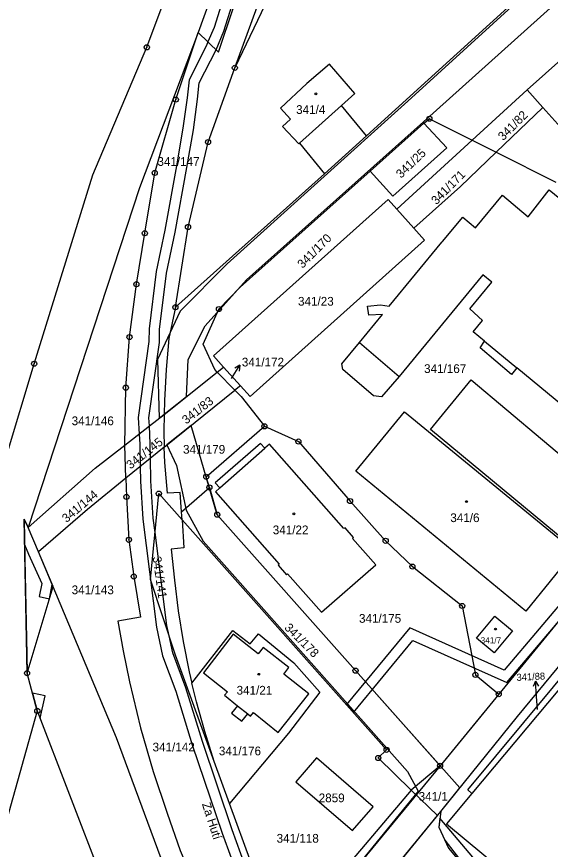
# Model space of a CAD drawing. Extents: x -562167 to -556918, y -1077891 to -1070763.
# Drawn here: x -558021.9 to -557917.9, y -1073189.3 to -1073027.2 of the extents above; entities that cross this region are included whole.
import ezdxf

# ---------------------------------------------------------------- set-up
doc = ezdxf.new("R2010")
doc.units = 0
for name, color, linetype in [('Hranice parcel', 7, 'Continuous'), ('Parcelní čísla', 7, 'Continuous'), ('Pop  PČ popisy', 7, 'Continuous'), ('Vnitřní kresba', 7, 'Continuous'), ('Věcná břemena k části', 7, 'Continuous'), ('Značky bodu BP', 7, 'Continuous'), ('Značky budov', 7, 'Continuous')]:
    doc.layers.add(name, color=color, linetype=linetype)

msp = doc.modelspace()

# ---------------------------------------------------------------- linework, layer by layer
at = {"layer": 'Hranice parcel'}
for p, q in [((-557978.42, -1073007.88), (-557986.56, -1073030.25)), ((-557907.19, -1073008.05), (-557953.76, -1073050.4)), ((-557990.91, -1073043.32), (-557986.56, -1073030.25)), ((-557933.18, -1073051.22), (-557922.44, -1073041.43)), ((-557922.44, -1073041.43), (-557919.41, -1073044.83)), ((-557919.41, -1073044.83), (-557928.5, -1073053.57)), ((-557909.28, -1073056.19), (-557919.41, -1073044.83)), ((-557953.04, -1073057.23), (-557942.56, -1073047.93)), ((-557953.76, -1073050.4), (-557961.97, -1073057.78)), ((-557947.88, -1073064.63), (-557933.18, -1073051.22)), ((-557933.18, -1073051.22), (-557928.5, -1073053.57)), ((-557928.5, -1073053.57), (-557916.86, -1073059.41)), ((-557961.97, -1073057.78), (-557990.99, -1073083.73)), ((-557978.35, -1073079.84), (-557953.04, -1073057.23)), ((-557947.88, -1073064.63), (-557944.57, -1073068.33)), ((-557982.82, -1073096.35), (-557981.6, -1073095.38)), ((-557978.3, -1073099.03), (-557981.6, -1073095.38)), ((-557993.2, -1073104.6), (-557982.82, -1073096.35)), ((-557982.82, -1073096.35), (-557983.3, -1073095.86)), ((-557979.38, -1073099.9), (-557982.82, -1073096.35)), ((-558000.85, -1073110.59), (-558000.64, -1073099.4)), ((-557993.15, -1073110.97), (-557979.38, -1073099.9)), ((-557978.3, -1073099.03), (-557979.38, -1073099.9)), ((-557979.38, -1073099.9), (-557978.18, -1073101.14)), ((-557993.14, -1073101.88), (-557993.2, -1073104.6)), ((-557978.18, -1073101.14), (-557973.65, -1073106.92)), ((-558000.64, -1073117.04), (-558000.85, -1073110.59)), ((-557993.15, -1073110.97), (-558000.64, -1073117.04)), ((-557993.03, -1073113.93), (-557993.15, -1073110.97)), ((-558000.64, -1073117.04), (-558000.52, -1073120.65)), ((-557989.8, -1073123.55), (-557984.37, -1073118.82)), ((-557989.7, -1073125.09), (-557989.8, -1073123.55)), ((-558017.66, -1073131.36), (-558019.64, -1073126.64)), ((-557905.93, -1073145.77), (-557933.22, -1073178.38)), ((-557928, -1073159.05), (-557939.43, -1073173)), ((-557980.44, -1073180.31), (-557983.42, -1073172.14)), ((-557939.43, -1073173), (-557945.06, -1073177.72)), ((-557957.38, -1073203.94), (-557939.31, -1073181.91))]:
    msp.add_line(p, q, dxfattribs=at)
for points in [[(-558023.91, -1073118.12), (-558023.87, -1073112.67), (-558018.5, -1073094.73), (-558007.07, -1073057.93), (-557996.56, -1073033.14), (-557957.14, -1072927.95), (-557940.88, -1072884.8)], [(-557828.77, -1072964.03), (-557832.02, -1072960.41), (-557849.58, -1072976.05), (-557850.4, -1072975.22), (-557852.25, -1072973.18), (-557902.56, -1073018.36), (-557900.74, -1073020.37), (-557901.86, -1073021.37), (-557901.06, -1073022.27), (-557922.44, -1073041.43)], [(-557986.56, -1073030.25), (-557982.57, -1073034.1), (-557976.61, -1073016.24), (-557974.32, -1073010.73), (-557971.33, -1073005.68), (-557965.93, -1072998.31), (-557952.35, -1072982.67), (-557941.8, -1072972.85)], [(-557979.41, -1073037.13), (-557974.34, -1073023.25), (-557969.19, -1073013.05), (-557961.67, -1072999.93), (-557956.79, -1072992.37), (-557951.58, -1072985.33)], [(-557958.24, -1072996.81), (-557969.89, -1073017.14), (-557979.41, -1073037.13)], [(-557986.56, -1073030.25), (-557997.97, -1073060.52), (-558019.64, -1073126.64)], [(-557990.99, -1073083.73), (-557988.53, -1073068.12), (-557984.62, -1073051.58), (-557979.41, -1073037.13)], [(-557953.76, -1073050.4), (-557958.64, -1073044.45), (-557956.03, -1073042.11), (-557960.96, -1073036.4), (-557965.35, -1073040.16), (-557970.52, -1073045), (-557968.56, -1073047.1), (-557970.12, -1073048.54), (-557966.96, -1073051.92), (-557966.81, -1073051.78), (-557961.97, -1073057.78)], [(-558000.64, -1073099.4), (-557999.93, -1073089.54), (-557998.58, -1073079.27), (-557996.94, -1073069.34), (-557995.02, -1073057.58), (-557990.91, -1073043.32)], [(-557942.56, -1073047.93), (-557938.12, -1073052.69), (-557948.63, -1073062.09), (-557953.04, -1073057.23)], [(-557942.56, -1073047.93), (-557941.51, -1073047.04), (-557933.18, -1073051.22)], [(-557928.5, -1073053.57), (-557935.44, -1073060.24), (-557944.57, -1073068.33)], [(-557907.63, -1073109.45), (-557924.45, -1073095.53), (-557925.5, -1073096.82), (-557931.62, -1073091.61), (-557930.74, -1073090.33), (-557932.96, -1073088.5), (-557931.14, -1073086.3), (-557933.62, -1073084.07), (-557929.32, -1073078.85), (-557931.08, -1073077.41), (-557947.37, -1073097.24), (-557950.81, -1073101.21), (-557952.39, -1073100.98), (-557958.38, -1073095.85), (-557958.54, -1073094.77), (-557955.13, -1073090.62), (-557950.62, -1073085.14), (-557953.33, -1073085.27), (-557953.54, -1073083.52), (-557951.06, -1073083.26), (-557949.32, -1073083.55), (-557939.09, -1073071.1), (-557938.95, -1073070.95), (-557934.98, -1073066.23), (-557932.52, -1073068.28), (-557927.25, -1073061.91), (-557922.29, -1073066.12), (-557918.16, -1073060.91), (-557884.44, -1073088.22)], [(-557981.6, -1073095.38), (-557983.55, -1073093.22), (-557949.57, -1073062.74), (-557947.88, -1073064.63)], [(-557944.57, -1073068.33), (-557942.47, -1073070.68), (-557976.44, -1073101.09), (-557978.3, -1073099.03)], [(-557983.3, -1073095.86), (-557985.61, -1073090.94), (-557982.51, -1073084.09), (-557978.35, -1073079.84)], [(-557990.99, -1073083.73), (-557992.26, -1073089.81), (-557992.79, -1073095.87), (-557993.14, -1073101.88)], [(-557912.95, -1073130.96), (-557941.31, -1073107.54), (-557933.38, -1073097.86), (-557912.52, -1073115.4)], [(-558000.85, -1073110.59), (-557996.03, -1073106.85), (-557993.2, -1073104.6)], [(-557993.2, -1073104.6), (-557993.27, -1073107.88), (-557993.15, -1073110.97)], [(-557913.26, -1073131.24), (-557922.7, -1073142.9), (-557955.83, -1073115.65), (-557946.34, -1073104.09), (-557913.26, -1073131.24)], [(-557984.37, -1073118.82), (-557984.98, -1073116.73), (-557973.65, -1073106.92)], [(-557973.65, -1073106.92), (-557967.03, -1073109.88), (-557956.97, -1073121.47), (-557950.03, -1073129.2), (-557944.82, -1073134.22), (-557935.12, -1073141.88), (-557932.55, -1073155.3), (-557928, -1073159.05)], [(-558019.64, -1073126.64), (-558006.61, -1073115.07), (-558000.85, -1073110.59)], [(-557969.37, -1073135.81), (-557969.15, -1073135.61), (-557962.54, -1073143.1), (-557951.95, -1073133.91), (-557956.51, -1073128.73), (-557956.29, -1073128.58), (-557957.94, -1073126.65), (-557958.16, -1073126.84), (-557972.65, -1073110.37), (-557973.57, -1073111.19), (-557974.4, -1073110.29), (-557983.25, -1073117.92), (-557982.35, -1073118.91), (-557983.2, -1073119.66), (-557970.77, -1073133.77), (-557970.99, -1073133.97), (-557969.37, -1073135.81)], [(-557989.8, -1073123.55), (-557990.05, -1073119.8), (-557992.55, -1073119.94), (-557993.03, -1073113.93)], [(-558000.64, -1073117.04), (-558008.11, -1073123.09), (-558017.66, -1073131.36)], [(-557984.37, -1073118.82), (-557982.83, -1073124.12), (-557955.89, -1073154.48), (-557939.43, -1073173)], [(-558000.52, -1073120.65), (-558000.04, -1073129.01), (-557999.11, -1073136.15), (-557997.8, -1073144.09), (-558002.18, -1073144.84), (-558001.16, -1073150.6), (-557999.9, -1073156.63), (-557997.77, -1073165.6), (-557995.29, -1073174.11), (-557992.59, -1073182.21), (-557990.03, -1073189.46), (-557987.35, -1073195.77), (-557983.68, -1073194.26), (-557982.33, -1073196.81), (-557981.76, -1073198.85), (-557981.57, -1073201.43), (-557982.14, -1073203.98), (-557983.75, -1073205.73), (-557985.87, -1073206.17)], [(-557983.42, -1073172.14), (-557990.96, -1073151.47), (-557995.82, -1073136.74), (-557994.21, -1073120.02), (-557989.7, -1073125.09)], [(-557896.87, -1073121.14), (-557897.99, -1073122.83), (-557900.41, -1073126.04), (-557904.25, -1073130.15), (-557928, -1073159.05)], [(-558017.89, -1073162.31), (-558019.89, -1073154.97), (-558020.46, -1073125.01), (-558019.64, -1073126.64)], [(-557989.7, -1073125.09), (-557989.34, -1073130.57), (-557991.78, -1073130.81), (-557991.16, -1073136.84), (-557990.48, -1073142.82), (-557989.46, -1073148.8), (-557988.32, -1073154.7), (-557987.77, -1073156.89)], [(-557945.06, -1073177.72), (-557951.46, -1073171.48), (-557949.84, -1073169.89), (-557989.7, -1073125.09)], [(-557988.88, -1073205.99), (-557991.98, -1073195.8), (-558002.46, -1073167.55), (-558017.66, -1073131.36)], [(-557939.31, -1073181.91), (-557924.34, -1073163.38), (-557903.65, -1073138.34), (-557899.86, -1073135.36), (-557897.5, -1073134.86), (-557893.95, -1073136.63), (-557873.45, -1073153.94), (-557872.45, -1073154.98)], [(-557925.34, -1073146.76), (-557928.91, -1073150.99), (-557932.3, -1073148.14), (-557928.73, -1073143.89), (-557925.34, -1073146.76)], [(-557933.22, -1073178.38), (-557934.05, -1073177.7), (-557906.42, -1073144.55), (-557905.54, -1073145.31)], [(-557987.77, -1073156.89), (-557979.78, -1073146.64), (-557976.42, -1073149.25), (-557974.83, -1073147.3), (-557967.94, -1073152.96), (-557962.85, -1073158.68), (-557968.95, -1073166.68), (-557980.44, -1073180.31)], [(-557970.95, -1073166.51), (-557965.02, -1073158.98), (-557969.85, -1073155.15), (-557968.89, -1073153.89), (-557973.86, -1073149.99), (-557974.84, -1073151.22), (-557979.76, -1073147.38), (-557985.54, -1073154.91), (-557980.86, -1073158.6), (-557981.39, -1073159.27), (-557978.88, -1073161.31), (-557980.03, -1073162.76), (-557978.05, -1073164.33), (-557976.9, -1073162.88), (-557976.34, -1073163.32), (-557975.78, -1073162.62), (-557970.95, -1073166.51)], [(-557983.42, -1073172.14), (-557985.27, -1073166.32), (-557986.86, -1073160.52), (-557987.77, -1073156.89)], [(-558017.89, -1073162.31), (-558032.09, -1073212.63), (-558035.15, -1073249.33), (-558039.97, -1073265.01), (-558041.24, -1073272.26), (-558045.55, -1073290.79), (-558055.77, -1073312.33), (-558066.64, -1073329.29), (-558067.37, -1073328.67), (-558071.91, -1073335.47), (-558071.45, -1073339.78), (-558072.38, -1073341.74), (-558078.52, -1073350.81)], [(-558017.89, -1073162.31), (-558005.3, -1073194.99), (-557999.34, -1073213.91)], [(-557963.49, -1073171.43), (-557967.51, -1073176.11), (-557956.46, -1073185.61), (-557952.45, -1073180.98), (-557963.49, -1073171.43)], [(-557945.06, -1073177.72), (-557964.79, -1073201.02), (-557968.13, -1073202.16), (-557970.23, -1073202.86)], [(-557933.22, -1073178.38), (-557938.16, -1073184.28), (-557924.03, -1073196.06), (-557926.52, -1073199.04), (-557917.14, -1073206.89), (-557900.5, -1073186.91)], [(-557970.23, -1073202.86), (-557971.99, -1073203.45), (-557980.44, -1073180.31)], [(-557939.31, -1073181.91), (-557939.68, -1073184.93), (-557937.77, -1073189.03), (-557931.69, -1073196.32), (-557936.68, -1073201.34), (-557924.3, -1073214.73)]]:
    msp.add_lwpolyline(points, dxfattribs=at)
at = {"layer": 'Pop  PČ popisy'}
for p, q in [((-557980.05, -1073097.58), (-557978.46, -1073095.03)), ((-557978.46, -1073095.03), (-557979.42, -1073095.62)), ((-557978.46, -1073095.03), (-557978.57, -1073096.15)), ((-557920.85, -1073156.54), (-557921.28, -1073157.57)), ((-557920.64, -1073159.53), (-557920.85, -1073156.54)), ((-557920.85, -1073156.54), (-557920.28, -1073157.5)), ((-557920.47, -1073162.06), (-557920.64, -1073159.53))]:
    msp.add_line(p, q, dxfattribs=at)
at = {"layer": 'Vnitřní kresba'}
for p, q in [((-557966.81, -1073051.78), (-557958.64, -1073044.45)), ((-557955.13, -1073090.62), (-557947.37, -1073097.24)), ((-557930.74, -1073090.33), (-557924.45, -1073095.53)), ((-557982.35, -1073118.91), (-557973.57, -1073111.19)), ((-557978.88, -1073161.31), (-557976.9, -1073162.88))]:
    msp.add_line(p, q, dxfattribs=at)
at = {"layer": 'Věcná břemena k části'}
for points in [[(-557822.11, -1072958), (-557824.2, -1072954.83), (-557832.14, -1072950.96), (-557839.71, -1072951.32), (-557846.26, -1072953.78), (-557883.58, -1072987.07), (-557945.69, -1073043.61), (-557980.87, -1073075.26), (-557990.05, -1073084.52), (-557994.46, -1073093.88), (-557994.12, -1073105.33), (-557988.84, -1073101.13), (-557988.53, -1073093.9), (-557985.16, -1073087.37), (-557977.13, -1073078.4), (-557942.64, -1073047.63), (-557878.66, -1072990.23), (-557843.73, -1072959.02), (-557840.12, -1072957.18), (-557833.96, -1072956.11), (-557830.07, -1072957.65), (-557825.42, -1072960.99)], [(-557985.61, -1073129.28), (-557959.92, -1073158.14), (-557945.8, -1073174.09), (-557943.7, -1073177.96), (-557960.77, -1073198.93), (-557964.79, -1073201.02), (-557971.99, -1073203.45), (-557986.64, -1073206.33), (-557988.88, -1073205.99), (-557985.92, -1073215.71), (-557980.83, -1073211.55), (-557974.16, -1073210.07), (-557963.9, -1073207.49), (-557961.96, -1073206.66), (-557959.95, -1073205.6), (-557957.38, -1073203.94), (-557939.31, -1073181.91), (-557935.6, -1073177.31), (-557955.89, -1073154.48), (-557982.83, -1073124.12), (-557987.89, -1073106.75), (-557992.63, -1073110.55), (-557990.75, -1073114.56), (-557988.87, -1073123.27)], [(-557944.74, -1073148.58), (-557926.4, -1073156.82), (-557898.45, -1073123.82), (-557890.09, -1073120.19), (-557888.89, -1073117.48), (-557899.68, -1073122.17), (-557926.95, -1073154.37), (-557945.32, -1073146.12), (-557957.67, -1073161.09), (-557956.32, -1073162.6)], [(-558019.89, -1073154.97), (-558014.83, -1073138.1), (-558017.66, -1073131.36), (-558019.64, -1073126.64), (-558020.46, -1073125.01), (-558020.31, -1073132.76), (-558019.96, -1073151.35)], [(-558014.99, -1073137.73), (-558017.66, -1073131.36), (-558019.64, -1073126.64), (-558020.46, -1073125.01), (-558020.36, -1073129.9), (-558019.58, -1073131.83), (-558016.98, -1073137.52), (-558017.5, -1073140.07), (-558015.54, -1073140.47)], [(-558018.83, -1073158.85), (-558017.89, -1073162.31), (-558017.34, -1073163.73), (-558016.36, -1073159.37)], [(-557945.06, -1073177.72), (-557964.79, -1073201.02), (-557968.13, -1073202.16), (-557971.99, -1073203.45), (-557986.64, -1073206.33), (-557988.88, -1073205.99), (-557985.92, -1073215.71), (-557980.83, -1073211.55), (-557965.16, -1073207.75), (-557957.1, -1073203.71), (-557939.95, -1073182.7)]]:
    msp.add_lwpolyline(points, close=True, dxfattribs=at)
for points in [[(-557979.03, -1073015.14), (-557983.45, -1073029.27), (-557984.64, -1073032.1), (-557984.93, -1073032.8), (-557988.33, -1073039.46), (-557988.69, -1073042.96), (-557989.51, -1073048.86), (-557990.79, -1073056.2), (-557993.03, -1073068.72), (-557994.75, -1073076.78), (-557996.11, -1073087.91), (-557996.14, -1073090.43), (-557998.23, -1073105.17), (-557998.05, -1073108.42), (-557997.93, -1073110.42), (-557997.85, -1073114.78), (-557997.8, -1073117.59), (-557997.33, -1073124.98), (-557994.66, -1073146.04), (-557993.47, -1073151.61), (-557990.92, -1073158.47), (-557987.69, -1073168.93), (-557981.87, -1073186.12), (-557978.4, -1073195.75)], [(-557976.54, -1073194.83), (-557979.93, -1073185.45), (-557985.74, -1073168.29), (-557988.98, -1073157.81), (-557991.5, -1073151.04), (-557992.21, -1073147.68), (-557992.63, -1073145.7), (-557994.94, -1073127.56), (-557995.29, -1073124.78), (-557995.75, -1073117.5), (-557995.83, -1073113.14), (-557995.89, -1073110.35), (-557996.03, -1073106.85), (-557996.18, -1073105.25), (-557994.09, -1073090.59), (-557994.06, -1073088.05), (-557992.72, -1073077.12), (-557991.02, -1073069.12), (-557988.77, -1073056.56), (-557987.49, -1073049.18), (-557986.65, -1073043.21), (-557986.33, -1073040.05), (-557983.05, -1073033.64), (-557981.53, -1073029.97), (-557977.08, -1073015.78)], [(-557957.38, -1073203.94), (-557939.31, -1073181.91), (-557924.34, -1073163.38), (-557903.65, -1073138.34), (-557899.86, -1073135.36), (-557897.5, -1073134.86), (-557893.95, -1073136.63), (-557876.59, -1073151.28), (-557875.07, -1073152.58), (-557873.45, -1073153.94), (-557872.45, -1073154.98), (-557868.31, -1073151.46), (-557870.27, -1073149.44), (-557875.14, -1073146.31), (-557882.72, -1073138.43), (-557890.2, -1073132), (-557891.89, -1073129.49), (-557893.05, -1073127.79), (-557904.25, -1073130.15), (-557939.43, -1073173), (-557960.77, -1073198.93)], [(-557904.25, -1073130.15), (-557939.43, -1073173), (-557960.77, -1073198.93)], [(-557957.1, -1073203.71), (-557939.31, -1073181.91), (-557924.34, -1073163.38), (-557903.65, -1073138.34)], [(-557926.3, -1073198.78), (-557939.46, -1073183.17), (-557939.68, -1073184.93), (-557938.49, -1073187.46), (-557931.69, -1073196.32)]]:
    msp.add_lwpolyline(points, dxfattribs=at)
at = {"layer": 'Značky bodu BP'}
for centre, radius in [((-557996.56, -1073033.14), 0.5), ((-557996.56, -1073033.14), 0.0303), ((-557979.41, -1073037.13), 0.5), ((-557979.41, -1073037.13), 0.0303), ((-557990.91, -1073043.32), 0.5), ((-557990.91, -1073043.32), 0.0303), ((-557941.51, -1073047.04), 0.5), ((-557941.51, -1073047.04), 0.0303), ((-557984.62, -1073051.58), 0.5), ((-557984.62, -1073051.58), 0.0303), ((-557995.02, -1073057.58), 0.5), ((-557995.02, -1073057.58), 0.0303), ((-557988.53, -1073068.12), 0.5), ((-557996.94, -1073069.34), 0.5), ((-557996.94, -1073069.34), 0.0303), ((-557988.53, -1073068.12), 0.0303), ((-557998.58, -1073079.27), 0.5), ((-557998.58, -1073079.27), 0.0303), ((-557990.99, -1073083.73), 0.5), ((-557990.99, -1073083.73), 0.0303), ((-557982.51, -1073084.09), 0.5), ((-557982.51, -1073084.09), 0.0303), ((-557999.93, -1073089.54), 0.5), ((-557999.93, -1073089.54), 0.0303), ((-558018.5, -1073094.73), 0.5), ((-558018.5, -1073094.73), 0.0303), ((-558000.64, -1073099.4), 0.5), ((-558000.64, -1073099.4), 0.0303), ((-557973.65, -1073106.92), 0.5), ((-557973.65, -1073106.92), 0.0303), ((-557967.03, -1073109.88), 0.5), ((-557967.03, -1073109.88), 0.0303), ((-557984.98, -1073116.73), 0.5), ((-557984.98, -1073116.73), 0.0303), ((-557994.21, -1073120.02), 0.5), ((-557984.37, -1073118.82), 0.5), ((-557984.37, -1073118.82), 0.0303), ((-558000.52, -1073120.65), 0.5), ((-558000.52, -1073120.65), 0.0303), ((-557994.21, -1073120.02), 0.0303), ((-557956.97, -1073121.47), 0.5), ((-557956.97, -1073121.47), 0.0303), ((-557982.83, -1073124.12), 0.5), ((-557982.83, -1073124.12), 0.0303), ((-558000.04, -1073129.01), 0.5), ((-558000.04, -1073129.01), 0.0303), ((-557950.03, -1073129.2), 0.5), ((-557950.03, -1073129.2), 0.0303), ((-557944.82, -1073134.22), 0.5), ((-557944.82, -1073134.22), 0.0303), ((-557999.11, -1073136.15), 0.5), ((-557999.11, -1073136.15), 0.0303), ((-557935.12, -1073141.88), 0.5), ((-557935.12, -1073141.88), 0.0303), ((-558019.89, -1073154.97), 0.5), ((-558019.89, -1073154.97), 0.0303), ((-557955.89, -1073154.48), 0.5), ((-557955.89, -1073154.48), 0.0303), ((-557932.55, -1073155.3), 0.5), ((-557932.55, -1073155.3), 0.0303), ((-557928, -1073159.05), 0.5), ((-557928, -1073159.05), 0.0303), ((-558017.89, -1073162.31), 0.5), ((-558017.89, -1073162.31), 0.0303), ((-557949.84, -1073169.89), 0.5), ((-557949.84, -1073169.89), 0.0303), ((-557951.46, -1073171.48), 0.5), ((-557951.46, -1073171.48), 0.0303), ((-557939.43, -1073173), 0.5), ((-557939.43, -1073173), 0.0303)]:
    msp.add_circle(centre, radius, dxfattribs=at)
at = {"layer": 'Značky budov'}
for centre in [(-557963.61, -1073042.2), (-557934.27, -1073121.57), (-557967.89, -1073123.96), (-557928.64, -1073146.39), (-557974.75, -1073155.18)]:
    msp.add_circle(centre, 0.175, dxfattribs=at)

# ---------------------------------------------------------------- texts
at = {"layer": 'Parcelní čísla'}
for s, height, p in [('341/4', 1.7, (-557967.47, -1073046.11)), ('341/147', 1.7, (-557994.49, -1073056.22)), ('341/23', 1.7, (-557967.1, -1073083.43)), ('341/172', 1.7, (-557978.04, -1073095.26)), ('341/167', 1.7, (-557942.54, -1073096.54)), ('341/146', 1.7, (-558011.2, -1073106.7)), ('341/179', 1.7, (-557989.5, -1073112.25)), ('341/6', 1.7, (-557937.43, -1073125.56)), ('341/22', 1.7, (-557972.02, -1073127.93)), ('341/143', 1.7, (-558011.2, -1073139.6)), ('341/175', 1.7, (-557955.22, -1073145.16)), ('341/7', 1.2, (-557931.53, -1073149.18)), ('341/21', 1.7, (-557979.07, -1073159.15)), ('341/142', 1.7, (-557995.43, -1073170.2)), ('341/176', 1.7, (-557982.52, -1073170.96)), ('341/1', 1.7, (-557943.6, -1073179.81)), ('2859', 1.7, (-557963.07, -1073180.1)), ('341/118', 1.7, (-557971.27, -1073187.97))]:
    msp.add_text(s, height=height, dxfattribs=at).set_placement(p)
for s, height, rotation, p in [('341/82', 1.7, 45, (-557927.13, -1073051.41)), ('341/25', 1.7, 44, (-557947.03, -1073058.74)), ('341/171', 1.7, 45, (-557940.15, -1073063.89)), ('341/170', 1.7, 45, (-557966.22, -1073076.28)), ('341/83', 1.7, 38, (-557988.88, -1073106.6)), ('341/145', 1.7, 38, (-557999.73, -1073115.36)), ('341/144', 1.7, 40, (-558012.21, -1073125.77)), ('341/141', 1.7, 278, (-557995.44, -1073132.36)), ('341/178', 1.7, 315, (-557969.87, -1073146.26)), ('341/88', 1.36, 3, (-557924.49, -1073156.48))]:
    msp.add_text(s, height=height, rotation=rotation, dxfattribs=at).set_placement(p)
at = {"layer": 'Pop  PČ popisy'}
msp.add_text('Za Hutí', height=1.7, rotation=288, dxfattribs=at).set_placement((-557985.84, -1073180.45))

doc.saveas('drawing.dxf')
